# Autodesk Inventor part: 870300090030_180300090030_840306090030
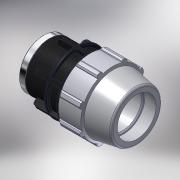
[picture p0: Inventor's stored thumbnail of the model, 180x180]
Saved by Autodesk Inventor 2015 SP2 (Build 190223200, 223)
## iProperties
Created: 2017-02
Part Number: 870300090030_180300090030_840306090030
Material: PVC-Piping
Description: PLASSON FEMALE ADAPTOR 90-3"
Document SubType Name: Modeling
Designer: KIM
Mass: 92.6774 g
Surface Area: 199.44 cm^2
Volume: 66.1981 cm^3
Density: 1.4 g/cm^3
Appearance: PTFE
Author: KIM
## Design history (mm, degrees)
derived "87030.ipt"
feature "Solid1::87030.ipt"
tag "TaggingFeature1"
body "Solid1"
other parameters: "d4" = 31.71429, "d5" = 55.5, "d7" = 152, "d9" = 31.71429, "d11" = 6.34286, "d12" = 121.6, "d13" = 120 deg, "d14" = 117, "d15" = 10 deg, "d16" = 136.8, "d18" = 4.5, "d19" = 35 deg, "d20" = 17.5 deg, "d21" = 141.36, "d23" = 0, "d25" = 360 deg, "d27" = 3.04, "d34" = 7.6, "d35" = 66.6, "d36" = 0, "d42" = 55.5, "d43" = 4.56, "d46" = 2.7, "d49" = 182, "d51" = 222, "d53" = 1.8, "d55" = 360 deg, "d62" = 84.926, "d63" = 84.926, "d64" = 74, "d65" = 7.6, "d69" = 109.44, "d70" = 3.8, "d71" = 12.6, "d72" = 0.5, "d73" = 1, "E_" = 152, "H_" = 222, "l_" = 182, "Rp_Rc_" = 84.926
